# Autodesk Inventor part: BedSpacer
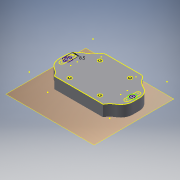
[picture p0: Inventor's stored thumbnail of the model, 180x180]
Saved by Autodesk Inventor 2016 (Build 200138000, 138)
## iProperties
Created: 2015-11
Part Number: BedSpacer
Material: Generic
Document SubType Name: Modeling
Designer: John
Density: 1 g/cm^3
Appearance: Default
Author: John
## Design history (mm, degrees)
workplane "Work Plane1"
sketch "Sketch1"
  geometry: L1 (41, 86)-(-5, 86) reference; L2 (-35, 45.641)-(-35, 54.331) reference; L3 (-15, 11)-(-15, -8) reference; L4 (-2, -10)-(-13, -10) reference; L5 (0, 0)-(0, -8) reference; L6 (0, 0)-(36, 0) reference; L7 (36, 0)-(36, -8) reference; L8 (49, -10)-(38, -10) reference; L9 (51, -8)-(51, 11) reference; L10 (71, 54.331)-(71, 45.641) reference; L11 (-27.75, 58.5)-(-27.75, 43.5) reference; L12 (-22.25, 43.5)-(-22.25, 58.5) reference; L13 (58.25, 58.5)-(58.25, 43.5) reference; L14 (63.75, 43.5)-(63.75, 58.5) reference; L15 (0.6, 38.5)-(0.6, 23.5) reference; L16 (-4.6, 23.5)-(-4.6, 38.5) reference; L17 (40.6, 38.5)-(40.6, 23.5) reference; L18 (35.4, 23.5)-(35.4, 38.5) reference; L19 (40.6, 78.5)-(40.6, 63.5) reference; L20 (35.4, 63.5)-(35.4, 78.5) reference; L21 (-4.6, 63.5)-(-4.6, 78.5) reference; L22 (0.6, 78.5)-(0.6, 63.5) reference; L23 (-2, 71)-(38, 71); L24 (38, 71)-(38, 31); L25 (38, 31)-(-2, 31); L26 (-2, 31)-(-2, 71); L27 (-5, 82)-(41, 82); L28 (67, 54.331)-(67, 45.641); L29 (47, 11)-(47, -6); L30 (47, -6)-(40, -6); L31 (40, -6)-(40, 4); L32 (40, 4)-(-4, 4); L33 (-4, 4)-(-4, -6); L34 (-4, -6)-(-11, -6); L35 (-11, -6)-(-11, 11); L36 (-31, 45.641)-(-31, 54.331); L37 (-14.215, 23)-(50.215, 23); C1 r 2.6 at (-2, 31); C2 r 2.6 at (-2, 71); C3 r 2.6 at (38, 71); C4 r 2.6 at (38, 31); A1 r 20 centre (51, 54.331) between (71, 54.331) and (58.99, 72.666) reference; A2 r 20 centre (66.981, 91) between (49.66, 81) and (58.99, 72.666) reference; A3 r 10 centre (41, 76) between (49.66, 81) and (41, 86) reference; A4 r 10 centre (-5, 76) between (-5, 86) and (-13.66, 81) reference; A5 r 20 centre (-30.981, 91) between (-22.99, 72.666) and (-13.66, 81) reference; A6 r 20 centre (-15, 54.331) between (-22.99, 72.666) and (-35, 54.331) reference; A7 r 20 centre (-15, 45.641) between (-35, 45.641) and (-25, 28.321) reference; A8 r 20 centre (-35, 11) between (-15, 11) and (-25, 28.321) reference; A9 r 2 centre (-13, -8) between (-15, -8) and (-13, -10) reference; A10 r 2 centre (-2, -8) between (-2, -10) and (0, -8) reference; A11 r 2 centre (38, -8) between (36, -8) and (38, -10) reference; A12 r 2 centre (49, -8) between (49, -10) and (51, -8) reference; A13 r 20 centre (71, 11) between (61, 28.321) and (51, 11) reference; A14 r 20 centre (51, 45.641) between (61, 28.321) and (71, 45.641) reference; A15 r 2.75 centre (-25, 43.5) between (-27.75, 43.5) and (-22.25, 43.5) reference; A16 r 2.75 centre (-25, 58.5) between (-22.25, 58.5) and (-27.75, 58.5) reference; A17 r 2.75 centre (61, 43.5) between (58.25, 43.5) and (63.75, 43.5) reference; A18 r 2.75 centre (61, 58.5) between (63.75, 58.5) and (58.25, 58.5) reference; A19 r 2.6 centre (-2, 23.5) between (-4.6, 23.5) and (0.6, 23.5) reference; A20 r 2.6 centre (-2, 38.5) between (0.6, 38.5) and (-4.6, 38.5) reference; A21 r 2.6 centre (38, 23.5) between (35.4, 23.5) and (40.6, 23.5) reference; A22 r 2.6 centre (38, 38.5) between (40.6, 38.5) and (35.4, 38.5) reference; A23 r 2.6 centre (38, 63.5) between (35.4, 63.5) and (40.6, 63.5) reference; A24 r 2.6 centre (38, 78.5) between (40.6, 78.5) and (35.4, 78.5) reference; A25 r 2.6 centre (-2, 78.5) between (0.6, 78.5) and (-4.6, 78.5) reference; A26 r 2.6 centre (-2, 63.5) between (-4.6, 63.5) and (0.6, 63.5) reference; A27 r 16 centre (-15, 54.331) between (-21.392, 68.999) and (-31, 54.331); A28 r 24 centre (-30.981, 91) between (-21.392, 68.999) and (-10.196, 79); A29 r 6 centre (-5, 76) between (-5, 82) and (-10.196, 79); A30 r 6 centre (41, 76) between (46.196, 79) and (41, 82); A31 r 24 centre (66.981, 91) between (46.196, 79) and (57.392, 68.999); A32 r 16 centre (51, 54.331) between (67, 54.331) and (57.392, 68.999); A33 r 16 centre (51, 45.641) between (59, 31.785) and (67, 45.641); A34 r 24 centre (71, 11) between (59, 31.785) and (47, 11); A35 r 24 centre (-35, 11) between (-11, 11) and (-23, 31.785); A36 r 16 centre (-15, 45.641) between (-31, 45.641) and (-23, 31.785); 1 further point
  constraints: 30 end point, 22 point on circle, 14 centre point, 4 equal radius, 2 coincident, 2 parallel, 1 horizontal, 1 horizontal alignment, 1 midpoint, 1 perpendicular, 1 vertical alignment, 19 other
  dimensions: "d0" = 40 distance of L23.start L23.end; "d1" = 40 distance of L25.end L23.start; "d2" = 4 radial gap between concentric circles of A6 A27
  node "Reference1"
workplane "Work Plane2"
sketch "Sketch2"
  geometry: C1 r 2.6 at (-2, 31) reference; C2 r 2.6 at (38, 31) reference; C3 r 2.6 at (-2, 71) reference; C4 r 2.6 at (38, 71) reference; 1 further point
extrude "Extrusion1" new body sketch "Sketch1" distance "d3" = 15; taper "d4" = 0 deg
extrude "Extrusion2" cut sketch "Sketch2" stored distance "d5" = 15; taper "d6" = 0 deg
sketch "Sketch3"
  geometry: L1 (-31, 54.331)-(-31, 45.641) reference; L2 (-14.215, 23)-(50.215, 23) reference; L3 (67, 45.641)-(67, 54.331) reference; L4 (41, 82)-(-5, 82) reference; L5 (-22.25, 43.5)-(-22.25, 58.5) reference; L6 (-27.75, 58.5)-(-27.75, 43.5) reference; L7 (63.75, 43.5)-(63.75, 58.5) reference; L8 (58.25, 58.5)-(58.25, 43.5) reference; L9 (-29.05, 48.662)-(-29.05, 53.338); L10 (-29.05, 53.338)-(-25, 55.677); L11 (-25, 55.677)-(-20.95, 53.338); L12 (-20.95, 53.338)-(-20.95, 48.662); L13 (-20.95, 48.662)-(-25, 46.323); L14 (-25, 46.323)-(-29.05, 48.662); L15 (65.05, 48.662)-(61, 46.323); L16 (61, 46.323)-(56.95, 48.662); L17 (56.95, 48.662)-(56.95, 53.338); L18 (56.95, 53.338)-(61, 55.677); L19 (61, 55.677)-(65.05, 53.338); L20 (65.05, 53.338)-(65.05, 48.662); L21 (67, 45.641)-(67, 54.331) reference; C1 r 2.6 at (-2, 71) reference; C2 r 2.6 at (-2, 31) reference; C3 r 2.6 at (38, 31) reference; C4 r 2.6 at (38, 71) reference; C5 r 2.75 at (-25, 51); C6 r 2.75 at (61, 51); A1 r 16 centre (-15, 45.641) between (-31, 45.641) and (-23, 31.785) reference; A2 r 24 centre (-35, 11) between (-14.215, 23) and (-23, 31.785) reference; A3 r 24 centre (71, 11) between (59, 31.785) and (50.215, 23) reference; A4 r 16 centre (51, 45.641) between (59, 31.785) and (67, 45.641) reference; A5 r 16 centre (51, 54.331) between (67, 54.331) and (57.392, 68.999) reference; A6 r 24 centre (66.981, 91) between (46.196, 79) and (57.392, 68.999) reference; A7 r 6 centre (41, 76) between (46.196, 79) and (41, 82) reference; A8 r 6 centre (-5, 76) between (-5, 82) and (-10.196, 79) reference; A9 r 24 centre (-30.981, 91) between (-21.392, 68.999) and (-10.196, 79) reference; A10 r 16 centre (-15, 54.331) between (-21.392, 68.999) and (-31, 54.331) reference; A11 r 2.75 centre (-25, 43.5) between (-27.75, 43.5) and (-22.25, 43.5) reference; A12 r 2.75 centre (-25, 58.5) between (-22.25, 58.5) and (-27.75, 58.5) reference; A13 r 2.75 centre (61, 43.5) between (58.25, 43.5) and (63.75, 43.5) reference; A14 r 2.75 centre (61, 58.5) between (63.75, 58.5) and (58.25, 58.5) reference; 5 further points
  constraints: 24 end point, 3 parallel, 2 centre point, 2 coincident, 2 equal radius, 2 horizontal alignment, 2 midpoint, 2 vertical alignment, 26 other
  dimensions: "d7" = 8.1 distance between parallel lines of L12 L9
extrude "Extrusion3" cut sketch "Sketch3" distance "d8" = 10; taper "d9" = 0 deg
sketch "Sketch4"
  geometry: C1 r 2.75 at (-25, 51) reference; C2 r 2.75 at (61, 51) reference; 1 further point
extrude "Extrusion4" cut sketch "Sketch4" stored distance "d10" = 10; taper "d11" = 0 deg
fillet "Fillet1" dims "d12" = 10
sketch "Sketch5"
  geometry: L1 (67, 45.641)-(67, 54.331) reference; L2 (41, 82)-(-5, 82) reference; L3 (-31, 54.331)-(-31, 45.641) reference; L4 (-9.077, 23)-(45.077, 23) reference; L5 (65.05, 53.338)-(65.05, 48.662) reference; L6 (65.05, 48.662)-(61, 46.323) reference; L7 (61, 46.323)-(56.95, 48.662) reference; L8 (56.95, 48.662)-(56.95, 53.338) reference; L9 (56.95, 53.338)-(61, 55.677) reference; L10 (61, 55.677)-(65.05, 53.338) reference; L11 (-25, 46.323)-(-29.05, 48.662) reference; L12 (-29.05, 48.662)-(-29.05, 53.338) reference; L13 (-29.05, 53.338)-(-25, 55.677) reference; L14 (-25, 55.677)-(-20.95, 53.338) reference; L15 (-20.95, 53.338)-(-20.95, 48.662) reference; L16 (-20.95, 48.662)-(-25, 46.323) reference; L17 (-2, 49.986)-(38, 49.986); L18 (-2, 44.986)-(38, 44.986); L19 (38, 54.986)-(-2, 54.986); L20 (18, 64.986)-(18, 34.986); L21 (13, 64.986)-(13, 34.986); L22 (23, 34.986)-(23, 64.986); L23 (-31, 54.331)-(-31, 45.641) reference; C1 r 2.6 at (-2, 71) reference; C2 r 2.6 at (-2, 31) reference; C3 r 2.6 at (38, 31) reference; C4 r 2.6 at (38, 71) reference; A1 r 10 centre (45.077, 33) between (45.077, 23) and (52.701, 26.529) reference; A2 r 24 centre (71, 11) between (59, 31.785) and (52.701, 26.529) reference; A3 r 16 centre (51, 45.641) between (59, 31.785) and (67, 45.641) reference; A4 r 16 centre (51, 54.331) between (67, 54.331) and (57.392, 68.999) reference; A5 r 24 centre (66.981, 91) between (46.196, 79) and (57.392, 68.999) reference; A6 r 6 centre (41, 76) between (46.196, 79) and (41, 82) reference; A7 r 6 centre (-5, 76) between (-5, 82) and (-10.196, 79) reference; A8 r 24 centre (-30.981, 91) between (-21.392, 68.999) and (-10.196, 79) reference; A9 r 16 centre (-15, 54.331) between (-21.392, 68.999) and (-31, 54.331) reference; A10 r 16 centre (-15, 45.641) between (-31, 45.641) and (-23, 31.785) reference; A11 r 24 centre (-35, 11) between (-16.701, 26.529) and (-23, 31.785) reference; A12 r 10 centre (-9.077, 33) between (-16.701, 26.529) and (-9.077, 23) reference; A13 r 5 centre (-2, 49.986) between (-2, 54.986) and (-2, 44.986); A14 r 5 centre (38, 49.986) between (38, 44.986) and (38, 54.986); A15 r 5 centre (18, 64.986) between (23, 64.986) and (13, 64.986); A16 r 5 centre (18, 34.986) between (13, 34.986) and (23, 34.986); 5 further points
  constraints: 16 end point, 8 point on circle, 8 tangent, 4 centre point, 4 midpoint, 2 parallel, 1 coincident, 1 equal radius, 1 horizontal, 1 horizontal alignment, 1 perpendicular, 1 vertical alignment
  dimensions: "d13" = 10 distance between parallel lines of L18 L19; "d14" = 40 distance of L17.start L17.end; "d15" = 30 distance of L20.start L20.end
extrude "Extrusion5" cut sketch "Sketch5" stored distance "d16" = 10; taper "d17" = 0 deg
fillet "Fillet2" dims "d18" = 5
sketch "Sketch6"
  geometry: L1 (28, 54.986)-(38, 54.986) reference; L2 (38, 44.986)-(28, 44.986) reference; L3 (23, 39.986)-(23, 34.986) reference; L4 (13, 34.986)-(13, 39.986) reference; L5 (8, 44.986)-(-2, 44.986) reference; L6 (-2, 54.986)-(8, 54.986) reference; L7 (13, 59.986)-(13, 64.986) reference; L8 (23, 64.986)-(23, 59.986) reference; L9 (67, 45.641)-(67, 54.331) reference; L10 (41, 82)-(-5, 82) reference; L11 (-31, 54.331)-(-31, 45.641) reference; L12 (-9.077, 23)-(45.077, 23) reference; L13 (65.05, 53.338)-(65.05, 48.662) reference; L14 (65.05, 48.662)-(61, 46.323) reference; L15 (61, 46.323)-(56.95, 48.662) reference; L16 (56.95, 48.662)-(56.95, 53.338) reference; L17 (56.95, 53.338)-(61, 55.677) reference; L18 (61, 55.677)-(65.05, 53.338) reference; L19 (-25, 46.323)-(-29.05, 48.662) reference; L20 (-29.05, 48.662)-(-29.05, 53.338) reference; L21 (-29.05, 53.338)-(-25, 55.677) reference; L22 (-25, 55.677)-(-20.95, 53.338) reference; L23 (-20.95, 53.338)-(-20.95, 48.662) reference; L24 (-20.95, 48.662)-(-25, 46.323) reference; C1 r 2.6 at (-2, 71) reference; C2 r 2.6 at (-2, 31) reference; C3 r 2.6 at (38, 31) reference; C4 r 2.6 at (38, 71) reference; C5 r 2.9 at (-2, 71); C6 r 2.9 at (38, 71); C7 r 2.9 at (-2, 31); C8 r 2.9 at (38, 31); A1 r 5 centre (28, 59.986) between (23, 59.986) and (28, 54.986) reference; A2 r 5 centre (38, 49.986) between (38, 44.986) and (38, 54.986) reference; A3 r 5 centre (28, 39.986) between (28, 44.986) and (23, 39.986) reference; A4 r 5 centre (18, 34.986) between (13, 34.986) and (23, 34.986) reference; A5 r 5 centre (8, 39.986) between (13, 39.986) and (8, 44.986) reference; A6 r 5 centre (-2, 49.986) between (-2, 54.986) and (-2, 44.986) reference; A7 r 5 centre (8, 59.986) between (8, 54.986) and (13, 59.986) reference; A8 r 5 centre (18, 64.986) between (23, 64.986) and (13, 64.986) reference; A9 r 10 centre (45.077, 33) between (45.077, 23) and (52.701, 26.529) reference; A10 r 24 centre (71, 11) between (59, 31.785) and (52.701, 26.529) reference; A11 r 16 centre (51, 45.641) between (59, 31.785) and (67, 45.641) reference; A12 r 16 centre (51, 54.331) between (67, 54.331) and (57.392, 68.999) reference; A13 r 24 centre (66.981, 91) between (46.196, 79) and (57.392, 68.999) reference; A14 r 6 centre (41, 76) between (46.196, 79) and (41, 82) reference; A15 r 6 centre (-5, 76) between (-5, 82) and (-10.196, 79) reference; A16 r 24 centre (-30.981, 91) between (-21.392, 68.999) and (-10.196, 79) reference; A17 r 16 centre (-15, 54.331) between (-21.392, 68.999) and (-31, 54.331) reference; A18 r 16 centre (-15, 45.641) between (-31, 45.641) and (-23, 31.785) reference; A19 r 24 centre (-35, 11) between (-16.701, 26.529) and (-23, 31.785) reference; A20 r 10 centre (-9.077, 33) between (-16.701, 26.529) and (-9.077, 23) reference; 1 further point
  constraints: 4 centre point, 3 equal radius
  dimensions: "d19" = 5.8 diameter of C5
extrude "Extrusion6" cut sketch "Sketch6" stored distance "d20" = 10; taper "d21" = 0 deg
body "Solid1"
node "Projected Loop1"
node "Reference2"
node "Reference3"
node "Reference4"
node "Reference5"
node "Reference6"
node "Reference7"
node "Reference8"
node "Reference9"
node "Projected Loop2"
node "Projected Loop3"
